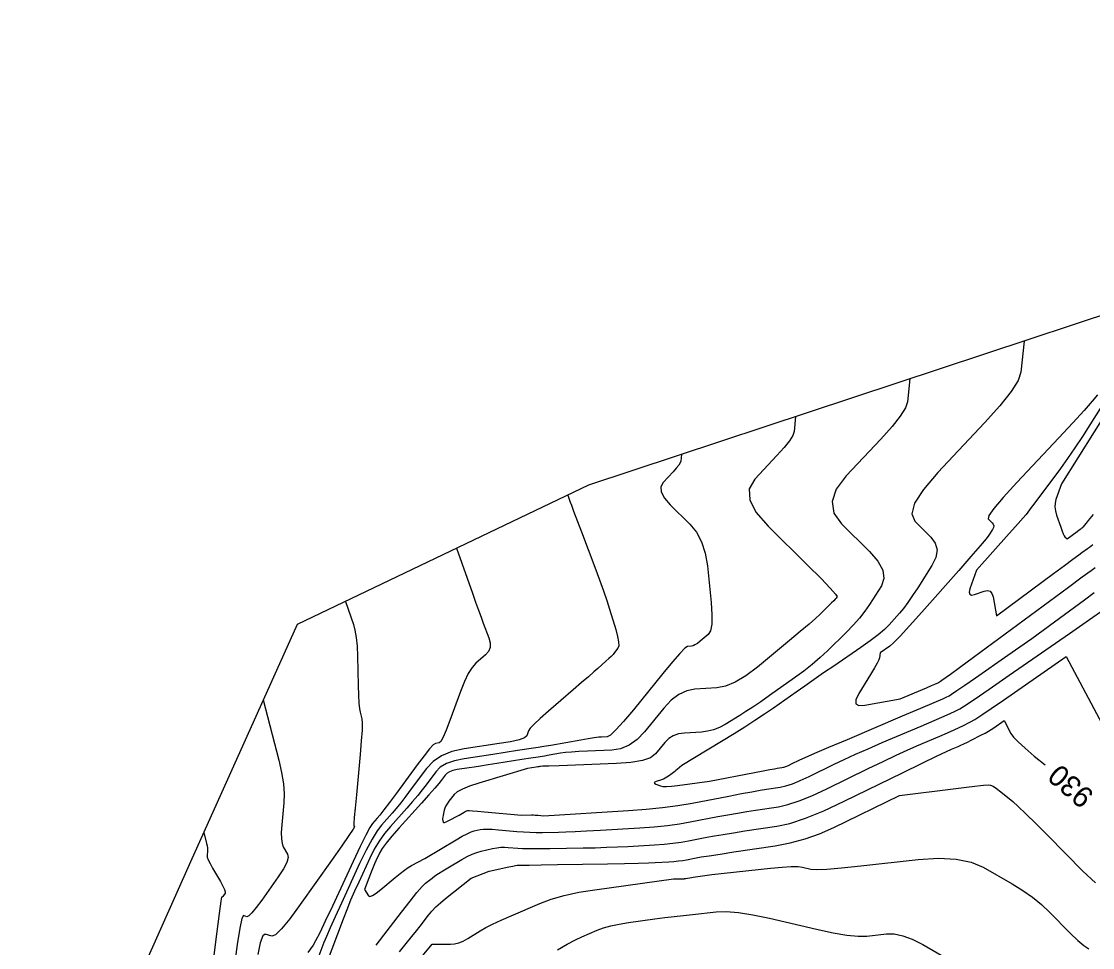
# Model space of a CAD drawing. Extents: x 2175772 to 2185556, y 721391 to 722853.
# Drawn here: x 2178684.5 to 2178826.6, y 722098.3 to 722221.1 of the extents above; entities that cross this region are included whole.
import ezdxf

# ---------------------------------------------------------------- set-up
doc = ezdxf.new("R2010")
doc.units = 0
for name, color, linetype in [('DT_X_Contour_Major', 7, 'Continuous'), ('DT_X_Contour_Minor', 7, 'Continuous'), ('DT_X_TIN_Hull', 7, 'Continuous')]:
    doc.layers.add(name, color=color, linetype=linetype)

msp = doc.modelspace()

# ---------------------------------------------------------------- linework, layer by layer
at = {"layer": 'DT_X_Contour_Major'}
for points in [[(2178828.96, 722171.98), (2178826.24, 722167.67), (2178825.24, 722166.09), (2178824.25, 722164.6), (2178823.27, 722163.2), (2178822.32, 722161.87), (2178818.95, 722157.33), (2178818.33, 722156.5), (2178817.93, 722155.96), (2178817.75, 722155.73), (2178816.36, 722154.18), (2178815.53, 722153.26), (2178811.18, 722148.39), (2178810.33, 722145.9), (2178810.23, 722145.45), (2178810.3, 722145.18), (2178810.54, 722145.08), (2178810.94, 722145.16), (2178812.23, 722145.6), (2178812.67, 722145.68), (2178813.01, 722145.58), (2178813.25, 722145.3), (2178813.39, 722144.85), (2178813.84, 722142.34), (2178821.4, 722147.93), (2178822.86, 722149), (2178823.97, 722149.82), (2178824.75, 722150.4), (2178825.19, 722150.72), (2178825.92, 722151.26), (2178826.19, 722151.45), (2178826.42, 722151.62), (2178826.63, 722151.77)], [(2178772.05, 722163.73), (2178771.96, 722162.85), (2178771.88, 722162.62), (2178771.69, 722162.3), (2178771.37, 722161.9), (2178770.94, 722161.42), (2178769.62, 722160.02), (2178769.31, 722159.44), (2178769.36, 722158.75), (2178769.79, 722157.95), (2178770.58, 722157.05), (2178773.17, 722154.49), (2178774.05, 722153.42), (2178774.73, 722152.14), (2178775.21, 722150.65), (2178775.49, 722148.94), (2178775.99, 722144.1), (2178776.1, 722142.47), (2178776.07, 722141.22), (2178775.9, 722140.34), (2178775.58, 722139.83), (2178774.54, 722138.97), (2178774.17, 722138.68), (2178773.85, 722138.48), (2178773.59, 722138.35), (2178773.37, 722138.3), (2178772.86, 722138.27), (2178772.51, 722138.03), (2178771.85, 722137.35), (2178770.87, 722136.23), (2178769.57, 722134.66), (2178765.68, 722129.88), (2178764.37, 722128.31), (2178763.36, 722127.19), (2178762.63, 722126.51), (2178762.21, 722126.28), (2178761.46, 722126.25), (2178761.08, 722126.22), (2178760.49, 722126.14), (2178759.69, 722126.02), (2178758.69, 722125.85), (2178754.71, 722125.15), (2178753.81, 722125), (2178753.05, 722124.87), (2178752.43, 722124.78), (2178750.3, 722124.45), (2178747.03, 722123.95), (2178743.25, 722123.38), (2178741.95, 722123.11), (2178740.89, 722122.73), (2178740.06, 722122.25), (2178739.47, 722121.65), (2178738.2, 722119.93), (2178737.68, 722119.25), (2178737.08, 722118.5), (2178736.39, 722117.69), (2178735.62, 722116.82), (2178733.44, 722114.4), (2178732.66, 722113.46), (2178731.95, 722112.45), (2178731.3, 722111.37), (2178730.71, 722110.21), (2178729.24, 722107.03), (2178728.69, 722105.83), (2178728.17, 722104.61), (2178727.66, 722103.36), (2178727.16, 722102.1), (2178724.91, 722096.14)], [(2178731.56, 722098.65), (2178734.9, 722103.02), (2178736.05, 722104.5), (2178736.97, 722105.64), (2178737.65, 722106.42), (2178738.1, 722106.86), (2178738.97, 722107.55), (2178739.35, 722107.83), (2178739.82, 722108.15), (2178740.39, 722108.51), (2178741.05, 722108.91), (2178742.94, 722110.03), (2178743.63, 722110.42), (2178744.29, 722110.73), (2178744.91, 722110.96), (2178745.49, 722111.13), (2178747, 722111.46), (2178747.56, 722111.56), (2178748.09, 722111.63), (2178748.6, 722111.65), (2178749.09, 722111.62), (2178750.37, 722111.51), (2178750.99, 722111.48), (2178751.91, 722111.46), (2178753.12, 722111.46), (2178754.61, 722111.48), (2178759, 722111.55), (2178760.6, 722111.58), (2178762.13, 722111.63), (2178763.57, 722111.68), (2178764.94, 722111.76), (2178768.48, 722111.97), (2178769.75, 722112.06), (2178770.93, 722112.18), (2178772, 722112.32), (2178772.97, 722112.49), (2178775.44, 722112.96), (2178776.44, 722113.15), (2178777.61, 722113.35), (2178778.95, 722113.57), (2178780.46, 722113.8), (2178784.69, 722114.43), (2178786.44, 722114.81), (2178788.52, 722115.49), (2178790.93, 722116.46), (2178793.66, 722117.73), (2178801.39, 722121.51), (2178803.97, 722122.77), (2178805.9, 722123.7), (2178807.2, 722124.33), (2178807.86, 722124.63), (2178808.77, 722125.01), (2178809.13, 722125.17), (2178809.53, 722125.36), (2178809.98, 722125.58), (2178810.48, 722125.83), (2178811.85, 722126.53), (2178812.34, 722126.78), (2178812.77, 722127.02), (2178813.15, 722127.25), (2178813.48, 722127.47), (2178814.86, 722128.43), (2178815.77, 722126.71), (2178816.11, 722126.25), (2178816.74, 722125.6), (2178817.66, 722124.77), (2178818.86, 722123.74), (2178820.29, 722122.56)], [(2178708.69, 722113.58), (2178709.06, 722112.14), (2178709.12, 722111.84), (2178709.17, 722111.58), (2178709.18, 722111.34), (2178709.18, 722111.12), (2178709.13, 722110.59), (2178709.16, 722110.33), (2178709.29, 722109.96), (2178709.53, 722109.47), (2178709.86, 722108.86), (2178710.9, 722107.09), (2178711.23, 722106.49), (2178711.44, 722106.03), (2178711.54, 722105.71), (2178711.51, 722105.53), (2178711.3, 722105.23), (2178711.23, 722105.13), (2178711.17, 722105.06), (2178711.13, 722105.02), (2178711.1, 722105.01), (2178711.06, 722105.02), (2178710.97, 722104.48), (2178710.75, 722102.84), (2178710.39, 722100.1), (2178709.9, 722096.27)]]:
    msp.add_lwpolyline(points, dxfattribs=at)
at = {"layer": 'DT_X_Contour_Minor'}
for points in [[(2178817.5, 722178.76), (2178817.08, 722174.62), (2178816.71, 722173.54), (2178815.79, 722172.06), (2178814.3, 722170.19), (2178812.26, 722167.92), (2178806.08, 722161.35), (2178804.15, 722159.09), (2178802.99, 722157.26), (2178802.62, 722155.85), (2178803.02, 722154.86), (2178805.13, 722152.78), (2178805.73, 722151.96), (2178805.96, 722151.06), (2178805.81, 722150.07), (2178805.29, 722149.01), (2178803.4, 722146.05), (2178802.71, 722145.01), (2178802.08, 722144.1), (2178801.49, 722143.32), (2178800.96, 722142.68), (2178799.59, 722141.14), (2178798.97, 722140.51), (2178798.15, 722139.81), (2178797.11, 722139.01), (2178795.86, 722138.13), (2178792.25, 722135.66), (2178790.92, 722134.75), (2178789.65, 722133.87), (2178788.43, 722133.02), (2178787.27, 722132.21), (2178784.25, 722130.09), (2178783.07, 722129.27), (2178781.81, 722128.44), (2178780.46, 722127.57), (2178779.03, 722126.68), (2178772.12, 722122.46), (2178771.48, 722121.93), (2178771.33, 722121.81), (2178771.17, 722121.69), (2178771, 722121.56), (2178770.82, 722121.42), (2178770.32, 722121.05), (2178770.12, 722120.92), (2178769.9, 722120.8), (2178769.67, 722120.69), (2178769.41, 722120.6), (2178768.71, 722120.38), (2178768.51, 722120.29), (2178768.44, 722120.21), (2178768.48, 722120.12), (2178768.66, 722120.02), (2178769.28, 722119.77), (2178769.59, 722119.7), (2178770.08, 722119.69), (2178770.73, 722119.73), (2178771.55, 722119.82), (2178775.76, 722120.39), (2178781.75, 722121.55), (2178782.9, 722121.77), (2178783.78, 722121.94), (2178784.41, 722122.05), (2178784.77, 722122.11), (2178785.37, 722122.2), (2178785.62, 722122.26), (2178785.92, 722122.36), (2178786.26, 722122.49), (2178786.65, 722122.68), (2178787.75, 722123.21), (2178788.46, 722123.54), (2178789.74, 722124.1), (2178791.62, 722124.91), (2178794.07, 722125.95), (2178801.4, 722129.06), (2178803.82, 722130.09), (2178805.6, 722130.85), (2178806.72, 722131.33), (2178807.19, 722131.54), (2178807.57, 722131.74), (2178807.89, 722131.94), (2178808.59, 722132.41), (2178809.65, 722133.13), (2178811.07, 722134.12), (2178815.36, 722137.09), (2178816.95, 722138.2), (2178818.52, 722139.31), (2178820.05, 722140.41), (2178821.55, 722141.51), (2178825.51, 722144.43), (2178826.82, 722145.4)], [(2178802.35, 722173.75), (2178802.04, 722170.7), (2178801.77, 722169.9), (2178801.09, 722168.81), (2178799.99, 722167.43), (2178798.49, 722165.75), (2178793.92, 722160.9), (2178792.6, 722159.14), (2178792.05, 722157.49), (2178792.28, 722155.96), (2178793.28, 722154.53), (2178796.98, 722150.88), (2178798.12, 722149.57), (2178798.77, 722148.37), (2178798.92, 722147.28), (2178798.58, 722146.3), (2178797.01, 722143.85), (2178796.38, 722142.93), (2178795.66, 722142), (2178794.85, 722141.08), (2178793.95, 722140.16), (2178791.44, 722137.7), (2178790.46, 722136.78), (2178789.41, 722135.88), (2178788.27, 722134.98), (2178787.07, 722134.1), (2178783.75, 722131.76), (2178782.57, 722130.94), (2178781.51, 722130.23), (2178780.59, 722129.62), (2178779.79, 722129.12), (2178777.84, 722127.92), (2178777.09, 722127.52), (2178776.32, 722127.22), (2178775.52, 722127.02), (2178774.7, 722126.92), (2178772.46, 722126.78), (2178771.67, 722126.66), (2178770.97, 722126.41), (2178770.37, 722126.04), (2178769.86, 722125.53), (2178768.63, 722124.02), (2178767.96, 722123.51), (2178766.87, 722123.13), (2178765.35, 722122.87), (2178763.42, 722122.73), (2178755.83, 722122.45), (2178754.48, 722122.4), (2178753.66, 722122.37), (2178753.37, 722122.36), (2178753.31, 722122.35), (2178753.26, 722122.34), (2178753.15, 722122.32), (2178752.99, 722122.3), (2178752.78, 722122.26), (2178751.64, 722122.09), (2178745.19, 722120.13), (2178743.95, 722119.73), (2178742.99, 722119.34), (2178742.31, 722118.97), (2178741.91, 722118.63), (2178741.22, 722117.74), (2178740.98, 722117.41), (2178740.8, 722117.11), (2178740.67, 722116.83), (2178740.59, 722116.56), (2178740.45, 722115.88), (2178740.41, 722115.64), (2178740.38, 722115.45), (2178740.38, 722115.3), (2178740.39, 722115.2), (2178740.45, 722114.97), (2178740.51, 722114.92), (2178740.64, 722114.93), (2178740.84, 722115), (2178741.12, 722115.14), (2178742.56, 722115.91), (2178743.22, 722116.3), (2178743.35, 722116.38), (2178743.46, 722116.43), (2178743.54, 722116.47), (2178743.6, 722116.49), (2178743.73, 722116.52), (2178743.9, 722116.52), (2178744.33, 722116.49), (2178745, 722116.44), (2178745.93, 722116.35), (2178750.82, 722115.91), (2178752.15, 722115.92), (2178752.42, 722115.92), (2178752.66, 722115.91), (2178752.86, 722115.9), (2178753.03, 722115.89), (2178753.75, 722115.82), (2178765.02, 722116.5), (2178767.36, 722116.67), (2178769.55, 722116.89), (2178771.59, 722117.17), (2178773.49, 722117.49), (2178778.33, 722118.43), (2178780.01, 722118.75), (2178781.4, 722119.01), (2178782.51, 722119.21), (2178783.33, 722119.34), (2178785.14, 722119.61), (2178785.89, 722119.78), (2178786.78, 722120.07), (2178787.82, 722120.48), (2178788.99, 722121.03), (2178792.3, 722122.65), (2178793.63, 722123.28), (2178795.13, 722123.97), (2178796.81, 722124.71), (2178798.67, 722125.51), (2178803.86, 722127.71), (2178805.59, 722128.45), (2178806.91, 722129.02), (2178807.81, 722129.42), (2178808.28, 722129.64), (2178808.99, 722130), (2178809.6, 722130.38), (2178810.9, 722131.25), (2178812.87, 722132.6), (2178815.53, 722134.44), (2178823.53, 722139.98), (2178826.17, 722141.82), (2178828.1, 722143.15)], [(2178827.24, 722171.64), (2178826.56, 722170.79), (2178825.47, 722169.56), (2178823.99, 722167.93), (2178822.11, 722165.91), (2178816.54, 722160), (2178814.74, 722158.04), (2178813.51, 722156.58), (2178812.85, 722155.63), (2178812.76, 722155.19), (2178813.27, 722154.68), (2178813.42, 722154.48), (2178813.48, 722154.26), (2178813.44, 722154.02), (2178813.31, 722153.76), (2178812.85, 722153.04), (2178812.47, 722152.55), (2178811.68, 722151.6), (2178810.46, 722150.21), (2178808.84, 722148.36), (2178803.95, 722142.83), (2178802.31, 722141), (2178801.06, 722139.63), (2178800.19, 722138.73), (2178799.72, 722138.31), (2178798.41, 722137.41), (2178798.35, 722136.75), (2178798.26, 722136.5), (2178798.03, 722136.06), (2178797.66, 722135.41), (2178797.14, 722134.56), (2178795.57, 722132.01), (2178795.18, 722131.2), (2178795.19, 722130.67), (2178795.59, 722130.43), (2178796.39, 722130.47), (2178801.06, 722131.31), (2178804.55, 722132.8), (2178805.21, 722133.07), (2178805.69, 722133.28), (2178805.98, 722133.4), (2178806.09, 722133.45), (2178806.14, 722133.48), (2178806.18, 722133.5), (2178806.28, 722133.57), (2178806.42, 722133.66), (2178806.61, 722133.8), (2178807.19, 722134.2), (2178807.74, 722134.59), (2178808.94, 722135.47), (2178810.79, 722136.84), (2178813.31, 722138.69), (2178820.88, 722144.28), (2178823.39, 722146.13), (2178825.23, 722147.49), (2178826.41, 722148.36), (2178826.93, 722148.74)], [(2178828.99, 722170.17), (2178822.49, 722159.84), (2178821.74, 722157.74), (2178821.62, 722157.27), (2178821.6, 722156.77), (2178821.66, 722156.23), (2178821.82, 722155.66), (2178822.37, 722154.09), (2178822.56, 722153.57), (2178822.71, 722153.18), (2178822.83, 722152.93), (2178822.91, 722152.8), (2178823.23, 722152.53), (2178824.57, 722153.52), (2178824.83, 722153.71), (2178825.02, 722153.85), (2178825.14, 722153.94), (2178825.2, 722153.98), (2178825.27, 722154.03), (2178825.31, 722154.06), (2178825.36, 722154.11), (2178825.43, 722154.19), (2178825.52, 722154.3), (2178825.77, 722154.62), (2178826.05, 722154.96), (2178826.71, 722155.76)], [(2178787.2, 722168.74), (2178787, 722166.77), (2178786.83, 722166.26), (2178786.39, 722165.55), (2178785.68, 722164.66), (2178784.71, 722163.59), (2178781.77, 722160.46), (2178781.05, 722159.19), (2178781.11, 722157.72), (2178781.94, 722156.06), (2178783.54, 722154.2), (2178788.84, 722148.98), (2178790.57, 722147.26), (2178791.79, 722146), (2178792.5, 722145.22), (2178792.7, 722144.9), (2178792.56, 722144.67), (2178792.45, 722144.54), (2178792.26, 722144.32), (2178791.97, 722144.03), (2178791.58, 722143.64), (2178790.43, 722142.51), (2178789.85, 722141.98), (2178788.98, 722141.22), (2178787.82, 722140.24), (2178786.37, 722139.04), (2178782.13, 722135.54), (2178780.6, 722134.38), (2178779.19, 722133.54), (2178777.91, 722133), (2178776.75, 722132.78), (2178773.83, 722132.6), (2178772.75, 722132.39), (2178771.7, 722131.9), (2178770.69, 722131.14), (2178769.71, 722130.1), (2178767.16, 722126.95), (2178766.16, 722125.91), (2178765.11, 722125.16), (2178763.99, 722124.69), (2178762.81, 722124.5), (2178759.58, 722124.39), (2178758.45, 722124.34), (2178757.48, 722124.27), (2178756.68, 722124.19), (2178756.03, 722124.1), (2178754.53, 722123.84), (2178753.88, 722123.73), (2178753.06, 722123.6), (2178752.07, 722123.44), (2178750.9, 722123.26), (2178747.57, 722122.74), (2178746.41, 722122.56), (2178745.4, 722122.4), (2178744.56, 722122.27), (2178743.89, 722122.17), (2178742.3, 722121.93), (2178741.75, 722121.82), (2178741.3, 722121.66), (2178740.96, 722121.45), (2178740.71, 722121.2), (2178740.17, 722120.48), (2178739.86, 722120.09), (2178739.32, 722119.46), (2178738.56, 722118.59), (2178737.57, 722117.48), (2178734.63, 722114.22), (2178733.65, 722113.1), (2178732.89, 722112.18), (2178732.35, 722111.46), (2178732.05, 722110.94), (2178731.53, 722109.84), (2178731.35, 722109.42), (2178731.16, 722108.99), (2178730.98, 722108.56), (2178730.81, 722108.12), (2178730.03, 722106.05), (2178730.55, 722105.21), (2178730.73, 722105.13), (2178731.07, 722105.24), (2178731.55, 722105.54), (2178732.18, 722106.04), (2178734.06, 722107.61), (2178734.73, 722108.16), (2178735.31, 722108.6), (2178735.81, 722108.95), (2178736.24, 722109.21), (2178738.03, 722110.16), (2178742.16, 722112.62), (2178742.97, 722113.09), (2178743.64, 722113.44), (2178744.17, 722113.68), (2178744.55, 722113.81), (2178745.37, 722113.99), (2178745.75, 722114.04), (2178746.28, 722114.05), (2178746.96, 722114.03), (2178747.79, 722113.96), (2178750.2, 722113.75), (2178751.09, 722113.68), (2178751.96, 722113.63), (2178752.8, 722113.61), (2178753.62, 722113.61), (2178755.75, 722113.64), (2178756.7, 722113.67), (2178757.94, 722113.72), (2178759.47, 722113.8), (2178761.3, 722113.91), (2178766.55, 722114.22), (2178768.45, 722114.36), (2178770.19, 722114.53), (2178771.79, 722114.74), (2178773.23, 722114.99), (2178776.88, 722115.7), (2178778.22, 722115.95), (2178779.51, 722116.18), (2178780.73, 722116.39), (2178781.89, 722116.57), (2178784.92, 722117.02), (2178786.17, 722117.29), (2178787.65, 722117.78), (2178789.37, 722118.47), (2178791.32, 722119.38), (2178796.84, 722122.08), (2178798.8, 722123.02), (2178800.52, 722123.84), (2178802.01, 722124.52), (2178803.27, 722125.07), (2178806.31, 722126.36), (2178807.36, 722126.81), (2178808.22, 722127.19), (2178808.89, 722127.5), (2178809.38, 722127.73), (2178810.42, 722128.26), (2178810.99, 722128.59), (2178811.9, 722129.18), (2178813.16, 722130.03), (2178814.78, 722131.14), (2178823.11, 722136.92), (2178828.56, 722126.62)], [(2178756.98, 722158.34), (2178757.31, 722157.4), (2178757.45, 722157), (2178757.75, 722156.22), (2178758.79, 722153.48), (2178760.57, 722148.79), (2178761.2, 722147.12), (2178761.73, 722145.64), (2178762.17, 722144.34), (2178762.52, 722143.23), (2178763.34, 722140.5), (2178763.59, 722139.58), (2178763.72, 722138.86), (2178763.73, 722138.35), (2178763.62, 722138.03), (2178763.18, 722137.46), (2178762.99, 722137.22), (2178762.73, 722136.95), (2178762.42, 722136.65), (2178762.04, 722136.3), (2178760.96, 722135.34), (2178760.45, 722134.89), (2178759.73, 722134.26), (2178758.81, 722133.47), (2178757.69, 722132.5), (2178754.41, 722129.68), (2178753.32, 722128.72), (2178752.52, 722127.97), (2178752, 722127.42), (2178751.77, 722127.07), (2178751.53, 722126.4), (2178751.23, 722126.15), (2178750.52, 722125.9), (2178749.39, 722125.64), (2178747.86, 722125.38), (2178743.22, 722124.68), (2178741.6, 722124.32), (2178740.23, 722123.77), (2178739.1, 722123.03), (2178738.23, 722122.1), (2178736.22, 722119.38), (2178735.5, 722118.41), (2178734.83, 722117.55), (2178734.22, 722116.8), (2178733.66, 722116.15), (2178732.26, 722114.59), (2178731.68, 722113.83), (2178731.01, 722112.72), (2178730.24, 722111.27), (2178729.37, 722109.48), (2178726.94, 722104.23), (2178726.11, 722102.43), (2178725.45, 722100.95), (2178724.95, 722099.8), (2178724.62, 722098.99), (2178723.96, 722097.25)], [(2178742.22, 722151.28), (2178744.32, 722145.33), (2178744.75, 722144.12), (2178745.13, 722143.06), (2178745.47, 722142.13), (2178745.76, 722141.34), (2178746.49, 722139.42), (2178746.67, 722138.74), (2178746.66, 722138.13), (2178746.46, 722137.6), (2178746.07, 722137.15), (2178744.77, 722136.03), (2178744.28, 722135.49), (2178743.78, 722134.68), (2178743.26, 722133.62), (2178742.74, 722132.3), (2178741.32, 722128.43), (2178740.84, 722127.16), (2178740.44, 722126.25), (2178740.12, 722125.68), (2178739.9, 722125.48), (2178739.41, 722125.41), (2178739.12, 722125.21), (2178738.62, 722124.67), (2178737.91, 722123.78), (2178736.99, 722122.55), (2178734.25, 722118.82), (2178733.32, 722117.57), (2178732.59, 722116.59), (2178732.05, 722115.9), (2178731.71, 722115.49), (2178731.07, 722114.77), (2178730.72, 722114.26), (2178730.19, 722113.25), (2178729.45, 722111.76), (2178728.51, 722109.77), (2178725.75, 722103.82), (2178724.81, 722101.82), (2178724.07, 722100.29), (2178723.53, 722099.23), (2178723.18, 722098.64), (2178722.51, 722097.7)], [(2178727.47, 722144.23), (2178728.55, 722141.16), (2178728.75, 722140.41), (2178728.91, 722139.46), (2178729.02, 722138.3), (2178729.08, 722136.96), (2178729.18, 722133.1), (2178729.22, 722131.79), (2178729.28, 722130.76), (2178729.34, 722130.01), (2178729.42, 722129.54), (2178729.65, 722128.65), (2178729.7, 722128.11), (2178729.68, 722127.15), (2178729.59, 722125.76), (2178729.44, 722123.96), (2178728.93, 722118.61), (2178728.77, 722116.84), (2178728.66, 722115.57), (2178728.61, 722114.78), (2178728.61, 722114.49), (2178728.68, 722114.36), (2178728.51, 722114.05), (2178727.95, 722113.2), (2178726.99, 722111.81), (2178725.63, 722109.89), (2178721.49, 722104.04), (2178720.09, 722102.14), (2178719, 722100.8), (2178718.21, 722100.04), (2178717.73, 722099.85), (2178716.85, 722100.11), (2178716.52, 722099.88), (2178716.19, 722098.97), (2178715.86, 722097.41)], [(2178716.59, 722131.19), (2178718.64, 722123.18), (2178719.01, 722121.55), (2178719.25, 722120.06), (2178719.34, 722118.72), (2178719.31, 722117.54), (2178719.03, 722114.6), (2178718.96, 722113.59), (2178718.98, 722112.76), (2178719.07, 722112.13), (2178719.24, 722111.68), (2178719.79, 722110.73), (2178719.87, 722110.27), (2178719.69, 722109.61), (2178719.26, 722108.76), (2178718.57, 722107.71), (2178716.39, 722104.63), (2178715.66, 722103.63), (2178715.08, 722102.93), (2178714.67, 722102.53), (2178714.42, 722102.43), (2178713.95, 722102.57), (2178713.75, 722102.18), (2178713.47, 722100.91), (2178713.13, 722098.76), (2178712.71, 722095.72)], [(2178734.64, 722097.77), (2178735.53, 722098.86), (2178736.28, 722099.79), (2178736.89, 722100.56), (2178737.38, 722101.18), (2178738.48, 722102.63), (2178738.93, 722103.17), (2178739.47, 722103.73), (2178740.08, 722104.29), (2178740.77, 722104.86), (2178744.18, 722107.55), (2178746.55, 722108.47), (2178749.17, 722109.05), (2178749.67, 722109.15), (2178750.04, 722109.23), (2178750.28, 722109.27), (2178750.4, 722109.28), (2178750.54, 722109.27), (2178750.89, 722109.27), (2178751.86, 722109.28), (2178753.43, 722109.31), (2178755.61, 722109.34), (2178762.24, 722109.45), (2178764.5, 722109.49), (2178766.31, 722109.53), (2178767.67, 722109.57), (2178768.58, 722109.61), (2178770.4, 722109.72), (2178771.06, 722109.76), (2178771.66, 722109.83), (2178772.22, 722109.9), (2178772.72, 722109.98), (2178773.99, 722110.23), (2178774.66, 722110.35), (2178775.72, 722110.52), (2178777.17, 722110.74), (2178779.02, 722111.02), (2178784.47, 722111.83), (2178786.48, 722112.21), (2178788.46, 722112.74), (2178790.39, 722113.43), (2178792.28, 722114.26), (2178800.97, 722118.51), (2178808.45, 722119.41), (2178809.88, 722119.59), (2178810.97, 722119.72), (2178811.72, 722119.81), (2178812.12, 722119.86), (2178812.75, 722119.93), (2178813.04, 722119.89), (2178813.41, 722119.73), (2178813.87, 722119.43), (2178814.42, 722119), (2178816, 722117.69), (2178816.74, 722117.04), (2178817.76, 722116.07), (2178819.07, 722114.79), (2178820.66, 722113.18), (2178825.28, 722108.48), (2178826.97, 722106.92)], [(2178734.32, 722093.11), (2178738.97, 722098.79), (2178741.43, 722098.77), (2178741.96, 722098.82), (2178742.53, 722098.96), (2178743.11, 722099.2), (2178743.72, 722099.54), (2178745.37, 722100.57), (2178746.09, 722100.98), (2178747.01, 722101.45), (2178748.13, 722101.97), (2178749.45, 722102.56), (2178753.25, 722104.18), (2178754.77, 722104.75), (2178756.5, 722105.25), (2178758.43, 722105.67), (2178760.57, 722106.01), (2178771, 722107.44), (2178771.8, 722107.45), (2178771.95, 722107.45), (2178772.08, 722107.45), (2178772.16, 722107.46), (2178772.22, 722107.46), (2178772.33, 722107.47), (2178772.37, 722107.47), (2178772.4, 722107.47), (2178772.43, 722107.48), (2178772.46, 722107.48), (2178772.54, 722107.5), (2178772.63, 722107.51), (2178772.84, 722107.54), (2178773.17, 722107.59), (2178773.63, 722107.66), (2178776.07, 722108.02), (2178783.89, 722108.86), (2178785.41, 722109), (2178786.62, 722109.08), (2178787.52, 722109.08), (2178788.1, 722109.02), (2178789.24, 722108.75), (2178789.98, 722108.7), (2178791.32, 722108.75), (2178793.27, 722108.91), (2178795.83, 722109.17), (2178803.47, 722110.01), (2178806.16, 722110.18), (2178808.49, 722110.06), (2178810.47, 722109.66), (2178812.09, 722108.98), (2178815.94, 722106.77), (2178817.33, 722105.92), (2178818.62, 722105.01), (2178819.81, 722104.04), (2178820.9, 722103.01), (2178823.65, 722100.21), (2178824.62, 722099.28), (2178825.43, 722098.6), (2178826.11, 722098.18)], [(2178755.61, 722098.03), (2178756.91, 722098.78), (2178758, 722099.37), (2178758.86, 722099.78), (2178760.89, 722100.64), (2178761.72, 722100.95), (2178762.68, 722101.22), (2178763.79, 722101.46), (2178765.04, 722101.65), (2178768.54, 722102.13), (2178769.84, 722102.31), (2178771.1, 722102.47), (2178772.33, 722102.61), (2178773.53, 722102.74), (2178776.67, 722103.08), (2178777.99, 722103.12), (2178779.61, 722102.99), (2178781.52, 722102.69), (2178783.72, 722102.23), (2178789.99, 722100.76), (2178792.17, 722100.29), (2178794, 722099.98), (2178795.49, 722099.84), (2178796.64, 722099.87), (2178799.25, 722100.15), (2178800.28, 722100.14), (2178801.43, 722099.9), (2178802.68, 722099.43), (2178804.06, 722098.73), (2178807.87, 722096.54)]]:
    msp.add_lwpolyline(points, dxfattribs=at)
at = {"layer": 'DT_X_TIN_Hull'}
msp.add_lwpolyline([(2179107.62, 722089.39), (2179075.12, 722109.69), (2179069.22, 722113.13), (2179059.79, 722118.52), (2179054.81, 722121.98), (2179049.44, 722125.39), (2179049.52, 722126.42), (2178984.03, 722166.57), (2178919.21, 722205.54), (2178909.71, 722210.4), (2178906.79, 722212.51), (2178903.07, 722214.83), (2178899.76, 722216.57), (2178897.01, 722218.1), (2178892.62, 722221.15), (2178877.64, 722214.96), (2178841.51, 722186.7), (2178759.74, 722159.66), (2178721.08, 722141.18), (2178706.95, 722109.71), (2178684.5, 722059.42)], dxfattribs=at)

# ---------------------------------------------------------------- texts
at = {"layer": 'DT_X_Contour_Major'}
msp.add_text('930', height=2.8, rotation=138.8642, dxfattribs=at).set_placement((2178826.96, 722118.72))

doc.saveas('drawing.dxf')
